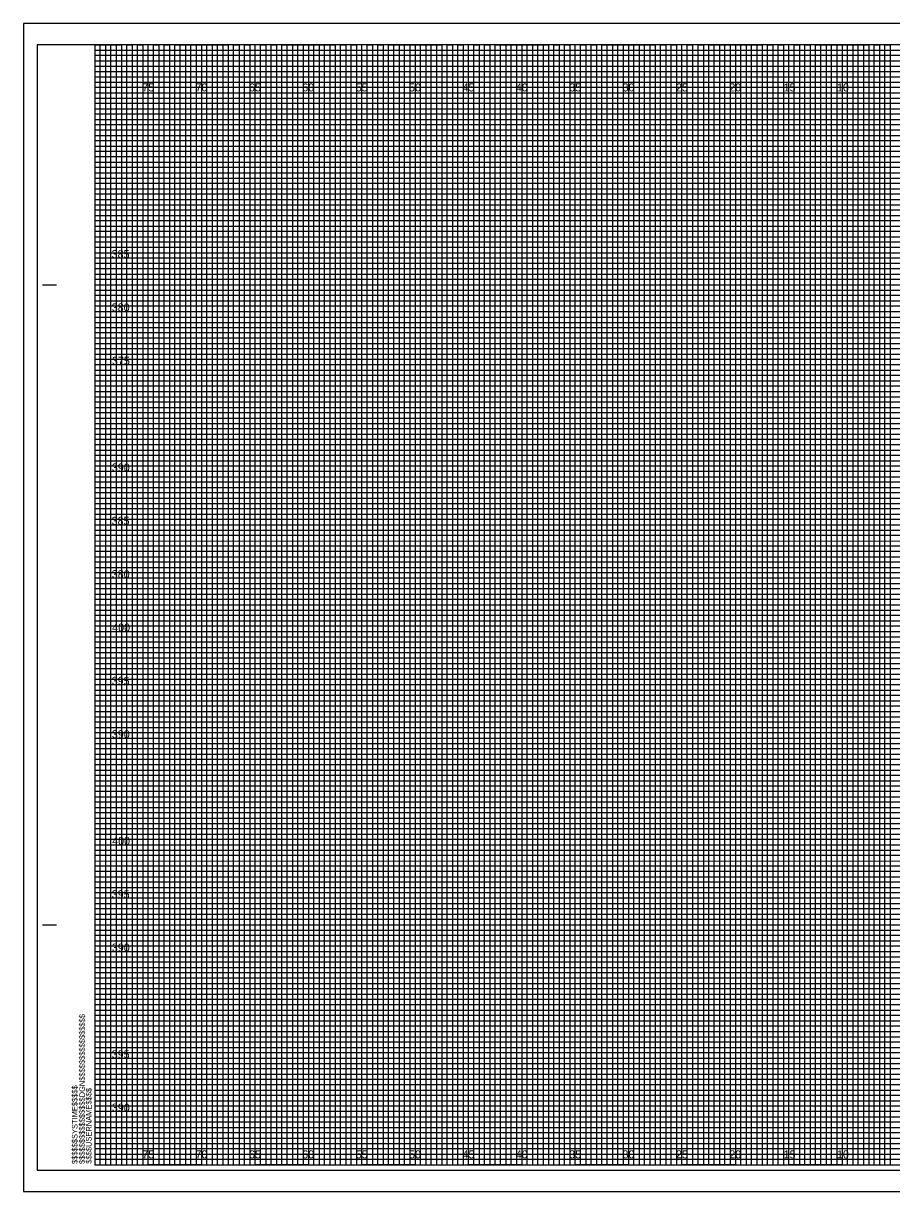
# Model space of a CAD drawing. Extents: x -7 to 162, y -2 to 107.
# Drawn here: x -6.7 to 74.6, y -2.5 to 107 of the extents above; entities that cross this region are included whole.
import ezdxf

# ---------------------------------------------------------------- set-up
doc = ezdxf.new("R2010")
doc.units = 0
for name, color, linetype in [('Prop XS Elevation Labels', 7, 'Continuous'), ('Prop XS Offset Labels', 7, 'Continuous'), ('Sheet Cross Section CELL', 7, 'Continuous'), ('Sheet Cross Section Grid Major CELL', 7, 'Continuous'), ('Sheet Cross Section Grid Middle CELL', 7, 'Continuous'), ('Sheet Cross Section Grid Minor 1 CELL', 7, 'Continuous'), ('Sheet Cross Section Grid Minor 2 CELL', 7, 'Continuous'), ('Sheet Plot Border Inside CELL', 7, 'Continuous'), ('Sheet Plot Border Outside CELL', 7, 'Continuous')]:
    doc.layers.add(name, color=color, linetype=linetype)

msp = doc.modelspace()

# ---------------------------------------------------------------- linework, layer by layer
at = {"layer": 'Sheet Cross Section CELL'}
for p, q in [((-4.9, 82.5), (-3.65, 82.5)), ((-4.85, 82.5), (-3.6, 82.5)), ((-4.9, 22.5), (-3.65, 22.5)), ((-4.85, 22.5), (-3.6, 22.5)), ((0, 0), (0, 0)), ((0, 0), (0, 0)), ((0, 0), (0, 0)), ((0, 0), (0, 0)), ((0, 0), (0, 0)), ((0, 0), (0, 0)), ((0, 0), (0, 0))]:
    msp.add_line(p, q, dxfattribs=at)
msp.add_lwpolyline([(160, 105), (0, 105), (0, 0), (160, 0)], close=True, dxfattribs=at)
at = {"layer": 'Sheet Cross Section Grid Major CELL'}
for p, q in [((5, 105), (0, 105)), ((5, 0), (5, 105)), ((15, 105), (10, 105)), ((10, 105), (10, 0)), ((15, 0), (15, 105)), ((25, 105), (20, 105)), ((20, 105), (20, 0)), ((25, 0), (25, 105)), ((35, 105), (30, 105)), ((30, 105), (30, 0)), ((35, 0), (35, 105)), ((45, 105), (40, 105)), ((40, 105), (40, 0)), ((45, 0), (45, 105)), ((55, 105), (50, 105)), ((50, 105), (50, 0)), ((55, 0), (55, 105)), ((65, 105), (60, 105)), ((60, 105), (60, 0)), ((65, 0), (65, 105)), ((75, 105), (70, 105)), ((70, 105), (70, 0)), ((10, 0), (5, 0)), ((20, 0), (15, 0)), ((30, 0), (25, 0)), ((40, 0), (35, 0)), ((50, 0), (45, 0)), ((60, 0), (55, 0)), ((70, 0), (65, 0))]:
    msp.add_line(p, q, dxfattribs=at)
for points in [[(160, 102.5), (160, 95), (0, 95)], [(0, 100), (160, 100)], [(0, 90), (160, 90), (160, 85), (0, 85)], [(0, 80), (160, 80), (160, 75), (0, 75)], [(0, 70), (160, 70), (160, 65), (0, 65)], [(0, 60), (160, 60), (160, 55), (0, 55)], [(0, 50), (160, 50), (160, 45), (0, 45)], [(0, 40), (160, 40), (160, 35), (0, 35)], [(0, 30), (160, 30), (160, 25), (0, 25)], [(0, 20), (160, 20), (160, 15), (0, 15)], [(0, 10), (160, 10), (160, 5), (0, 5)]]:
    msp.add_lwpolyline(points, dxfattribs=at)
at = {"layer": 'Sheet Cross Section Grid Middle CELL'}
for points in [[(0, 105), (2.5, 105), (2.5, 0), (7.5, 0), (7.5, 105), (12.5, 105), (12.5, 0), (17.5, 0), (17.5, 105), (22.5, 105), (22.5, 0), (27.5, 0), (27.5, 105), (32.5, 105), (32.5, 0), (37.5, 0), (37.5, 105), (42.5, 105), (42.5, 0), (47.5, 0), (47.5, 105), (52.5, 105), (52.5, 0), (57.5, 0), (57.5, 105), (62.5, 105), (62.5, 0), (67.5, 0), (67.5, 105), (72.5, 105), (72.5, 0), (77.5, 0)], [(0, 102.5), (137.5, 102.5)], [(0, 92.5), (160, 92.5), (160, 102.5)], [(160, 97.5), (0, 97.5)], [(0, 82.5), (160, 82.5), (160, 87.5), (0, 87.5)], [(0, 72.5), (160, 72.5), (160, 77.5), (0, 77.5)], [(0, 62.5), (160, 62.5), (160, 67.5), (0, 67.5)], [(0, 52.5), (160, 52.5), (160, 57.5), (0, 57.5)], [(0, 42.5), (160, 42.5), (160, 47.5), (0, 47.5)], [(0, 32.5), (160, 32.5), (160, 37.5), (0, 37.5)], [(0, 22.5), (160, 22.5), (160, 27.5), (0, 27.5)], [(0, 12.5), (160, 12.5), (160, 17.5), (0, 17.5)], [(0, 2.5), (160, 2.5), (160, 7.5), (0, 7.5)]]:
    msp.add_lwpolyline(points, dxfattribs=at)
at = {"layer": 'Sheet Cross Section Grid Minor 1 CELL'}
for p, q in [((0, 104.5), (110.95, 104.5)), ((110.95, 103.99), (0, 103.99)), ((0, 103.99), (0, 103.5)), ((0, 103.5), (110.95, 103.5)), ((110.95, 102.95), (0, 102.95)), ((0, 102.95), (0, 102)), ((0, 102), (160, 102))]:
    msp.add_line(p, q, dxfattribs=at)
for points in [[(0, 101.5), (135, 101.5), (160, 101.5)], [(160, 101), (0, 101)], [(0, 100.5), (160, 100.5)], [(160, 99.5), (0, 99.5)], [(0, 99), (160, 99)], [(160, 98.5), (0, 98.49)], [(0, 98), (160, 98)], [(160, 97), (0, 97)], [(0, 96.5), (160, 96.5), (160, 96), (0, 96)], [(0, 95.5), (160, 95.5), (160, 94.5), (0, 94.5)], [(0, 94), (160, 94), (160, 93.5), (0, 93.5)], [(0, 93), (160, 93), (160, 92), (0, 92)], [(0, 91.5), (160, 91.5), (160, 91), (0, 91)], [(0, 90.5), (160, 90.5), (160, 89.5), (0, 89.5)], [(0, 89), (160, 89), (160, 88.5), (0, 88.5)], [(0, 88), (160, 88), (160, 86.98), (160, 86.5), (160, 86), (0, 86)], [(0, 87), (160, 87), (160, 86.5), (0, 86.5)], [(0, 85.5), (160, 85.5), (160, 84.5), (0, 84.52)], [(0, 84.52), (160, 84.5), (160, 84), (0, 84)], [(0, 83.5), (160, 83.5), (160, 83), (0, 83)], [(0, 82), (160, 82), (160, 81.5), (0, 81.5)], [(0, 81), (160, 81), (160, 80.5), (0, 80.5)], [(-0.04, 79.45), (160, 79.45), (160, 78.94), (-0.04, 78.94)], [(0, 78.5), (160, 78.5), (160, 78), (0, 78)], [(0, 77), (160, 77), (160, 76.5), (0, 76.5)], [(0, 76), (160, 76), (160, 75.5), (0, 75.5)], [(0, 74.5), (160, 74.5), (160, 74), (0, 74)], [(0, 73.5), (160, 73.5), (160, 73), (0, 73)], [(0, 72), (160, 72), (160, 71.5), (0, 71.5)], [(0, 71), (160, 71), (160, 70.5), (0, 70.5)], [(0, 69.5), (160, 69.5), (159.99, 68.99), (0, 69)], [(0, 68.5), (160, 68.5), (160, 68), (0, 68)], [(0, 67), (160, 67), (160, 66.5), (0, 66.5)], [(0, 66), (160, 66), (160, 65.5), (0, 65.5)], [(0, 64.5), (160, 64.5), (160, 64), (0, 64)], [(0, 63.5), (160, 63.5), (160, 63), (0, 63)], [(0, 62), (160, 62), (160, 61.5), (0, 61.5)], [(0, 61), (160, 61), (160, 60.5), (0, 60.5)], [(0, 59.5), (160, 59.5), (160, 59), (0, 59)], [(0, 58.5), (160.03, 58.46), (160, 58), (0, 58)], [(0, 57), (160, 57), (160, 56.5), (0, 56.5)], [(0, 56), (160, 56), (160, 55.5), (0, 55.5)], [(0, 54.5), (160, 54.5), (160, 54), (0, 54)], [(0, 53.5), (160, 53.5), (160, 53), (0, 53)], [(0, 52), (160, 52), (160, 51.5), (0, 51.5)], [(0, 51), (160, 51), (160, 50.5), (0, 50.5)], [(0, 49.5), (160, 49.5), (160, 49), (0, 49)], [(0, 48.5), (160, 48.5), (160, 48), (0, 48)], [(0, 47), (160, 47), (160, 46.5), (0, 46.5)], [(0, 46), (160, 46), (160, 45.5), (0, 45.5)], [(0, 44.5), (160, 44.5), (160, 44), (0, 44)], [(0, 43.5), (160, 43.5), (160, 43), (0, 43)], [(0, 42), (160, 42), (160, 41.5), (0, 41.5)], [(0, 41), (160, 41), (160, 40.5), (0, 40.5)], [(0, 39.5), (160, 39.5), (159.99, 38.99), (0, 39)], [(0, 38.5), (160, 38.5), (160, 38), (0, 38)], [(0, 37), (160, 37), (160, 36.5), (0, 36.5)], [(0, 36), (160, 36), (160, 35.5), (0, 35.5)], [(0, 34.5), (160, 34.5), (160, 34), (0, 34)], [(0, 33.5), (160, 33.5), (160, 33), (0, 33)], [(0, 32), (160, 32), (160, 31.5), (0, 31.5)], [(0, 31), (160, 31), (160, 30.5), (0, 30.5)], [(0, 29.5), (160, 29.5), (160, 29), (0, 29)], [(0, 28.5), (160.03, 28.46), (160, 28), (0, 28)], [(0, 27), (160, 27), (160, 26.5), (0, 26.5)], [(0, 26), (160, 26), (160, 25.5), (0, 25.5)], [(0, 24.5), (160, 24.5), (160, 24), (0, 24)], [(0, 23.5), (160, 23.5), (160, 23), (0, 23)], [(0, 22), (160, 22), (160, 21.5), (0, 21.5)], [(0, 21), (160, 21), (160, 20.5), (0, 20.5)], [(0, 19.5), (160, 19.5), (160, 19), (0, 19)], [(0, 18.5), (160, 18.5), (160, 18), (0, 18)], [(0, 17), (160, 17), (160, 16.5), (0, 16.5)], [(0, 16), (160, 16), (160, 15.5), (0, 15.5)], [(0, 14.5), (160, 14.5), (160, 14), (0, 14)], [(0, 13.5), (160, 13.5), (160, 13), (0, 13)], [(0, 12), (160, 12), (160, 11.5), (0, 11.5)], [(0, 11), (160, 11), (160, 10.5), (0, 10.5)], [(0, 9.5), (160, 9.5), (160, 9), (0, 9)], [(0, 8.5), (160, 8.5), (160, 8), (0, 8)], [(0, 7), (160, 7), (160, 6.5), (0, 6.5)], [(0, 6), (160, 6), (160, 5.5), (0, 5.5)], [(0, 4.5), (160, 4.5), (160, 4), (0, 4)], [(0, 3.5), (160, 3.5), (160, 3), (0, 3)], [(0, 2), (160, 2), (160, 1.5), (0, 1.5)], [(0, 1), (160, 1), (160, 0.5), (0, 0.5)]]:
    msp.add_lwpolyline(points, dxfattribs=at)
at = {"layer": 'Sheet Cross Section Grid Minor 2 CELL'}
for points in [[(0, 0), (0.5, 0), (0.5, 105), (1, 105), (1, 0)], [(1, 0), (1.5, 0), (1.5, 105), (2, 105), (2, 0)], [(2.5, 0), (3, 0), (3, 105), (3.5, 105), (3.5, 0)], [(3.5, 0), (4, 0), (4, 105), (4.5, 105), (4.5, 0)], [(5, 0), (5.5, 0), (5.5, 105), (6, 105), (6, 0)], [(6, 0), (6.5, 0), (6.5, 105), (7, 105), (7, 0)], [(7.5, 0), (8, 0), (8, 105), (8.5, 105), (8.5, 0)], [(8.5, 0), (9, 0), (9, 105), (9.5, 105), (9.5, 0)], [(10, 0), (10.5, 0), (10.5, 105), (11, 105), (11, 0)], [(11, 0), (11.5, 0), (11.5, 105), (12, 105), (12, 0)], [(12.5, 0), (13, 0), (13, 105), (13.5, 105), (13.5, 0)], [(13.5, 0), (14, 0), (14, 105), (14.5, 105), (14.5, 0)], [(15, 0), (15.5, 0), (15.5, 105), (16, 105), (16, 0)], [(16, 0), (16.5, 0), (16.5, 105), (17, 105), (17, 0)], [(17.5, 0), (18, 0), (18, 105), (18.5, 105), (18.5, 0)], [(18.5, 0), (19, 0), (19, 105), (19.5, 105), (19.5, 0)], [(20, 0), (20.5, 0), (20.5, 105), (21, 105), (21, 0)], [(21, 0), (21.5, 0), (21.5, 105), (22, 105), (22, 0)], [(22.5, 0), (23, 0), (23, 105), (23.5, 105), (23.5, 0)], [(23.5, 0), (24, 0), (24, 105), (24.5, 105), (24.5, 0)], [(25, 0), (25.5, 0), (25.5, 105), (26, 105), (26, 0)], [(26, 0), (26.5, 0), (26.5, 105), (27, 105), (27, 0)], [(27.5, 0), (28, 0), (28, 105), (28.5, 105), (28.5, 0)], [(28.5, 0), (29, 0), (29, 105), (29.5, 105), (29.5, 0)], [(30, 0), (30.5, 0), (30.5, 105), (31, 105), (31, 0)], [(31, 0), (31.5, 0), (31.5, 105), (32, 105), (32, 0)], [(32.5, 0), (33, 0), (33, 105), (33.5, 105), (33.5, 0)], [(33.5, 0), (34, 0), (34, 105), (34.5, 105), (34.5, 0)], [(35, 0), (35.5, 0), (35.5, 105), (36, 105), (36, 0)], [(36, 0), (36.5, 0), (36.5, 105), (37, 105), (37, 0)], [(37.5, 0), (38, 0), (38, 105), (38.5, 105), (38.5, 0)], [(38.5, 0), (39, 0), (39, 105), (39.5, 105), (39.5, 0)], [(40, 0), (40.5, 0), (40.5, 105), (41, 105), (41, 0)], [(41, 0), (41.5, 0), (41.5, 105), (42, 105), (42, 0)], [(42.5, 0), (43, 0), (43, 105), (43.5, 105), (43.5, 0)], [(43.5, 0), (44, 0), (44, 105), (44.5, 105), (44.5, 0)], [(45, 0), (45.5, 0), (45.5, 105), (46, 105), (46, 0)], [(46, 0), (46.5, 0), (46.5, 105), (47, 105), (47, 0)], [(47.5, 0), (48, 0), (48, 105), (48.5, 105), (48.5, 0)], [(48.5, 0), (49, 0), (49, 105), (49.5, 105), (49.5, 0)], [(50, 0), (50.5, 0), (50.5, 105), (51, 105), (51, 0)], [(51, 0), (51.5, 0), (51.5, 105), (52, 105), (52, 0)], [(52.5, 0), (53, 0), (53, 105), (53.5, 105), (53.5, 0)], [(53.5, 0), (54, 0), (54, 105), (54.5, 105), (54.5, 0)], [(55, 0), (55.5, 0), (55.5, 105), (56, 105), (56, 0)], [(56, 0), (56.5, 0), (56.5, 105), (57, 105), (57, 0)], [(57.5, 0), (58, 0), (58, 105), (58.5, 105), (58.5, 0)], [(58.5, 0), (59, 0), (59, 105), (59.5, 105), (59.5, 0)], [(60, 0), (60.5, 0), (60.5, 105), (61, 105), (61, 0)], [(61, 0), (61.5, 0), (61.5, 105), (62, 105), (62, 0)], [(62.5, 0), (63, 0), (63, 105), (63.5, 105), (63.5, 0)], [(63.5, 0), (64, 0), (64, 105), (64.5, 105), (64.5, 0)], [(65, 0), (65.5, 0), (65.5, 105), (66, 105), (66, 0)], [(66, 0), (66.5, 0), (66.5, 105), (67, 105), (67, 0)], [(67.5, 0), (68, 0), (68, 105), (68.5, 105), (68.5, 0)], [(68.5, 0), (69, 0), (69, 105), (69.5, 105), (69.5, 0)], [(70, 0), (70.5, 0), (70.5, 105), (71, 105), (71, 0)], [(71, 0), (71.5, 0), (71.5, 105), (72, 105), (72, 0)], [(72.5, 0), (73, 0), (73, 105), (73.5, 105), (73.5, 0)], [(73.5, 0), (74, 0), (74, 105), (74.5, 105), (74.5, 0)]]:
    msp.add_lwpolyline(points, dxfattribs=at)
at = {"layer": 'Sheet Plot Border Inside CELL'}
msp.add_lwpolyline([(-5.4, -0.5), (161.2, -0.5), (161.2, 105), (-5.4, 105)], close=True, dxfattribs=at)
at = {"layer": 'Sheet Plot Border Outside CELL'}
msp.add_lwpolyline([(-6.7, -2.5), (161.65, -2.5), (161.65, 107), (-6.7, 107)], close=True, dxfattribs=at)

# ---------------------------------------------------------------- texts
at = {"layer": 'Prop XS Elevation Labels'}
for s, p in [('385', (1.57, 85)), ('380', (1.58, 80)), ('375', (1.6, 75)), ('390', (1.59, 65)), ('385', (1.57, 60)), ('380', (1.58, 55)), ('400', (1.62, 50)), ('395', (1.58, 45)), ('390', (1.59, 40)), ('400', (1.62, 30)), ('395', (1.58, 25)), ('390', (1.59, 20)), ('395', (1.58, 10)), ('390', (1.59, 5))]:
    msp.add_text(s, height=0.75, dxfattribs=at).set_placement(p)
at = {"layer": 'Prop XS Offset Labels'}
for s, p in [('75', (4.44, 100.62)), ('70', (9.43, 100.62)), ('65', (14.44, 100.62)), ('60', (19.43, 100.62)), ('55', (24.44, 100.62)), ('50', (29.43, 100.62)), ('45', (34.44, 100.62)), ('40', (39.43, 100.62)), ('35', (44.44, 100.62)), ('30', (49.43, 100.62)), ('25', (54.44, 100.62)), ('20', (59.43, 100.62)), ('15', (64.53, 100.62)), ('10', (69.52, 100.62)), ('75', (4.44, 0.62)), ('70', (9.43, 0.62)), ('65', (14.44, 0.62)), ('60', (19.43, 0.62)), ('55', (24.44, 0.62)), ('50', (29.43, 0.62)), ('45', (34.44, 0.62)), ('40', (39.43, 0.62)), ('35', (44.44, 0.62)), ('30', (49.43, 0.62)), ('25', (54.44, 0.62)), ('20', (59.43, 0.62)), ('15', (64.53, 0.62)), ('10', (69.52, 0.62))]:
    msp.add_text(s, height=0.75, dxfattribs=at).set_placement(p)
at = {"layer": 'Sheet Cross Section CELL'}
for s, p in [('$$$$$$$$$$$$$$$$DGN$$$$$$$$$$$$$$$$', (-0.94, 0.09)), ('$$$$$$SYSTIME$$$$$', (-1.63, 0.09)), ('$$$$USERNAME$$$$', (-0.31, 0.12))]:
    msp.add_text(s, height=0.525, rotation=90, dxfattribs=at).set_placement(p)

doc.saveas('drawing.dxf')
